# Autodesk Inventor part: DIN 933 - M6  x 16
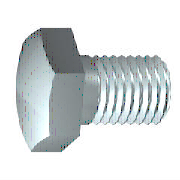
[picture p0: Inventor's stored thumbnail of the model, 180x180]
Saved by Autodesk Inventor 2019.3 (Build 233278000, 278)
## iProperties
Created: 2018-01
Part Number: DIN 933 - M6  x 16
Material: Ocel, měkká
Description: Šestihranný šroub
Document SubType Name: Modeling
Standard: DIN 933
Designer: B-hon
Standards Organization: DIN
Language: cs-CZ
Size Designation: M6  x 16
Categories: <MemberInstance><Categories><Category DisplayName="Spojovací materiál" InternalName="e4da775c-781d-43d5-af7c-5136215cf5a6" Mnemonic="FSTN"><Category DisplayName
Density: 7.85 g/cm^3
Appearance: Pololeštěná
IsCustomPart: 0
Author: B-hon
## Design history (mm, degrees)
sketch "Náčrt1"
  geometry: L1 (0, 4.35)-(0, 2.729); L2 (3, 3)-(16, 3); L3 (16, 3)-(16, 0); L4 (16, 0)-(-0.5, 0); L5 (-3.8, 0)-(19.3, 0) reference; L6 (-0.5, 0)-(-0.5, 4.35); L7 (-0.5, 4.35)-(0, 4.35); L8 (3, 3)-(2.386, 2.729); L9 (2.386, 2.729)-(0, 2.729); L10 (0, -0.87)-(0, 5.22) reference
  constraints: 16 end point, 2 collinear, 2 perpendicular, 1 parallel
  dimensions: "d0" = 16 distance between parallel lines of L3 L1 (= NLG); "d1" = 13 distance from line of L2.start L3 (= GEL); "d2" = 6 diameter of L2 L4 (= GD); "d9" = 0.5001 distance between parallel lines of L6 L1 (computed from SD); "d10" = 8.7 diameter of L7 L4 (= SD2); "d13" = 0.61355 horizontal distance of L2.start L8.end (computed from GAL); "d14" = 5.45873 diameter of L9 L4 (= BDM)
revolve "Těleso" sketch "Náčrt1" stored, may be unused: angle "d12" = 90 deg
sketch "Náčrt2"
  geometry: L1 (0, 5.774)-(5, 2.887); L2 (5, 2.887)-(5, -2.887); L3 (5, -2.887)-(0, -5.774); L4 (0, -5.774)-(-5, -2.887); L5 (-5, -2.887)-(-5, 2.887); L6 (-5, 2.887)-(0, 5.774); 2 further points
  constraints: 12 end point, 1 coincident, 1 vertical, 11 other
  dimensions: "d11" = 10 distance between parallel lines of L5 L2 (= SW)
extrude "Hlava" join sketch "Náčrt2" distance "d3" = 3.5 (= KOH - SD); taper "d4" = 0 deg
sketch "Náčrt4"
  geometry: L1 (-4, 5)-(-4, 5.774); L2 (-4, 5.774)-(-3.554, 5.774); L3 (-3.554, 5.774)-(-4, 5); L4 (-4.7, 0)-(0.2, 0) reference; L5 (-0.5, 5.774)-(-4, 5.774) reference; L6 (-4, 2.887)-(-4, 5.774) reference
  constraints: 6 end point, 2 collinear, 1 perpendicular, 1 vertical
  dimensions: "d5" = 30 deg angle of L3 L1 (= ANG1); "d19" = 10 diameter of L1.start L4 (= SW0)
revolve "Zkosení1" sketch "Náčrt4" stored, may be unused: angle "d21" = 90 deg
workplane "Work Plane1"
body "Solid1"
feature "Závit" dims "d15" = 13 (= GEL), "d16" = 0
chamfer "Zkosení2" distance "d6" = 0.61345 (= -0.5 x SPD + 0.5 x GD); stored, may be unused: second distance "d7" = 0.61355 (computed from GUL), angle "d55" = 45 deg
other parameters: "NLG" = 16 [user parameter; used in 1 equation term], "GD" = 6 (= NND) [user parameter; used in 2 equation terms], "BDM" = 5.45873 [user parameter; used in 1 equation term], "KOH" = 4 [user parameter; used in 1 equation term], "GEL" = 13 [user parameter; used in 2 equation terms], "SW" = 10 [user parameter; used in 2 equation terms], "SW0" = 10 [user parameter; used in 1 equation term], "SPD" = 4.7731 (= NND - 1.2269 x PTC) [user parameter; used in 1 equation term], "SD2" = 8.7 [user parameter; used in 1 equation term], "SD" = 0.5 [user parameter; used in 2 equation terms], "ANG1" = 30 deg [user parameter; used in 1 equation term], "GAL" = 0.61345 (= 0.61345 x PTC) [user parameter; used in 1 equation term], "GUL" = 0.61345 (= 0.61345 x PTC) [user parameter; used in 1 equation term], "d8" = 0, "RR" = 0.25 [user parameter], "d57" = 0, "d58" = 0, "GD1" = 4.7731 (= THREADDIA - 1.2269 x PTC) [user parameter], "THREADDIA" = 6 [user parameter; used in 1 equation term], "TOA" = 30 deg [user parameter], "PTC" = 1 [user parameter; used in 5 equation terms], "NND" = 6 [user parameter; used in 2 equation terms], "E0" = 11.55 (= 1.155 x SW) [user parameter]
